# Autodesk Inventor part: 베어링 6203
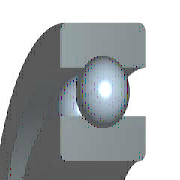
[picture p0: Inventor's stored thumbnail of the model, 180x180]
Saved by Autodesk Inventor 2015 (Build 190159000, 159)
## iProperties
IsCustomPart: 0
Created: 2018-09
Part Number: 베어링 6203
Material: 스테인리스강
Description: 깊은 그루브 볼 베어링
Document SubType Name: Modeling
Standard: KS B 2023
Standards Organization: KS
Language: ko-KR
Size Designation: 6203 - 17 x 40 x 12
Categories: <MemberInstance><Categories><Category DisplayName="샤프트 부품" InternalName="7f7aeb1f-a693-4053-b835-cee3144e0d98" Mnemonic="SHFT"><Category DisplayName="베어링" Inter
Density: 8.08 g/cm^3
Mass: 66.7997 g
Surface Area: 64.3582 cm^2
Volume: 8.26729 cm^3
Appearance: 보라색
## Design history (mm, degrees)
sketch "스케치" dims "d0" = 5.98 (= -0.26 x WD + 0.26 x BD)
  geometry: L1 (3.01, 14.25)-(8.99, 14.25); L2 (6, 14.25)-(6, 11.26); L3 (6, 14.25)-(6, 17.24); L4 (3.778, 12.249)-(0, 12.249); L5 (0, 8.5)-(12, 8.5); L6 (3.778, 16.251)-(0, 16.251); L7 (0, 20)-(12, 20); L8 (12, 8.5)-(12, 12.249); L9 (8.222, 12.249)-(12, 12.249); L10 (8.222, 16.251)-(12, 16.251); L11 (12, 20)-(12, 16.251); L12 (-1.4, 0)-(8.4, 0) reference; L13 (0, -0.3)-(0, 5.3) reference
  constraints: 22 end point, 4 point on line, 2 collinear, 2 perpendicular, 2 symmetric about line, 1 midpoint, 1 parallel, 14 other
  dimensions: "d9" = 17 diameter of L5 L12 (= WD); "d11" = 40 diameter of L7 L12 (= BD); "d12" = 12 distance between parallel lines of L8 L13 (= KB); "d13" = 24.498 diameter of L9 L12 (= 0.326 x BD + 0.674 x WD)
revolve "본체" stored, may be unused: angle "d6" = 90 deg
revolve "볼" stored, may be unused: angle "d7" = 90 deg
pattern_circular "IDS_ARRAYBALL[SIMPL:T]" dims angle "d3" = 360 deg
body "Solid1"
fillet "모깎기1" dims "d1" = 0.6 (= KRS)
other parameters: "WD" = 17 [user parameter; used in 5 equation terms], "BD" = 40 [user parameter; used in 5 equation terms], "KB" = 12 [user parameter; used in 1 equation term], "KRS" = 0.6 [user parameter; used in 1 equation term], "d4" = 0, "d5" = 0, "d8" = 0, "d14" = 0, "d15" = 0, "BBA" = 0 [user parameter], "BC0" = 4750000 [user parameter], "BC" = 9560000 [user parameter], "WR" = 8.5 (= 0.5 x WD) [user parameter]
